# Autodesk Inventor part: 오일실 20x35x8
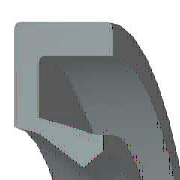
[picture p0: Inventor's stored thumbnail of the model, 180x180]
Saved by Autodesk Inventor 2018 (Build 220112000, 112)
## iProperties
IsCustomPart: 1
Created: 2012-02
Part Number: 오일실 20x35x8
Material: 고무
Description: 오일 실 - 비스프링, 조립 GA
Document SubType Name: Modeling
Standard: JIS B 2402
Designer: mdu-01
Standards Organization: JIS
Language: ko-KR
Size Designation: 20 35 8 A
Categories: <MemberInstance><Categories><Category DisplayName="샤프트 부품" InternalName="7f7aeb1f-a693-4053-b835-cee3144e0d98" Mnemonic="SHFT"><Category DisplayName="실링" Intern
Density: 0.93 g/cm^3
Appearance: Rubber-Black
Author: mdu-01
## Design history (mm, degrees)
body "Solid1"
revolve "회전1" stored, may be unused: angle "d27" = 360 deg
fillet "모깎기1" dims "d28" = 0.4 (= 0.05 x b)
sketch "스케치2"
  geometry: L1 (12.464, -6)-(13.214, -8); L2 (11.464, -5.5)-(12.464, -6); L3 (10, -2.2)-(11.464, -5.5); L4 (11.154, -1.2)-(10, -2.2); L5 (14.5, -7)-(11.154, -1.2); L6 (14.5, -0.4)-(14.5, -7); L7 (16, -0.4)-(14.5, -0.4); L8 (16, 0)-(16, -0.4); L9 (17.5, 0)-(16, 0); L10 (17.5, -8)-(17.5, 0); L11 (13.214, -8)-(17.5, -8); L12 (0, -9.6)-(0, 1.6) reference; L13 (28, 0)-(14, 0) reference
  constraints: 22 end point, 3 horizontal, 3 vertical
  dimensions: "d2" = 8 distance of L10.start L9.start (= b); "d4" = 1.5 distance of L9.start L8.start (= 0.1 x dd - 0.1 x Diam); "d6" = 0.4 distance of L8.start L7.start (= 0.05 x b); "d8" = 1.15385 horizontal distance of L4.start L3.start (= 0.0769231 x dd - 0.0769231 x Diam); "d10" = 1 vertical distance of L5.start L10.start (= 0.125 x b); "d12" = 1.5 distance of L7.start L6.start (= 0.1 x dd - 0.1 x Diam); "d14" = 0.8 vertical distance of L4.start L6.start (= 0.1 x b); "d16" = 4.28571 distance of L1.end L10.start (= 0.285714 x dd - 0.285714 x Diam); "d18" = 0.75 horizontal distance of L1.start L1.end (= 0.05 x dd - 0.05 x Diam); "d20" = 1 vertical distance of L4.start L3.start (= 0.125 x b); "d22" = 2 vertical distance of L1.start L1.end (= 0.25 x b); "d24" = 1 horizontal distance of L2.start L1.start (= 0.0666667 x dd - 0.0666667 x Diam); "d26" = 0.5 vertical distance of L2.start L1.start (= 0.0625 x b); "d29" = 0 distance between parallel lines of L13 L9; "d30" = 10 distance from line of L3.start L12 (= 0.5 x Diam); "d31" = 17.5 distance between parallel lines of L12 L10 (= 0.5 x dd)
other parameters: "dd" = 35 [user parameter; used in 7 equation terms], "b" = 8 [user parameter; used in 8 equation terms], "d1" = 8 (derived), "d3" = 2 (derived), "d5" = 0.4 (derived), "d7" = 1.53846 (derived), "d9" = 1 (derived), "d11" = 2 (derived), "d13" = 0.8 (derived), "d15" = 5.71429 (derived), "d17" = 1 (derived), "d19" = 1 (derived), "d21" = 2 (derived), "d23" = 1.33333 (derived), "d25" = 0.5 (derived), "d32" = 0
